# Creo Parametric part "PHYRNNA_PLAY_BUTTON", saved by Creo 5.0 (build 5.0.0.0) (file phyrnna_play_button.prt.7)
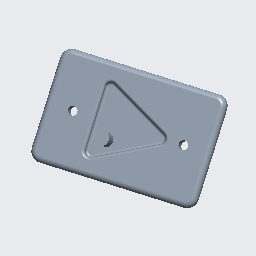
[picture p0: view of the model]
Units: Inch lbm Second (Pro/E Default); INCH, POUND, SECS

Created from: INLBS_PART_SOLID.PRT

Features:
  1. datum plane "RIGHT"
  2. datum plane "TOP"
  3. datum plane "FRONT"
  4. coordinate system
  5. sketch "Sketch 1"
  6. extrusion "Extrude 1"
  7. sketch "Sketch 2", "A_3"
  8. extruded cut "Extrude 2"
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
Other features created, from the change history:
  round "Round 1" (2 times)
  sketch "Sketch 3"
  extrusion "Extrude 3"
  round "Round 2"

Other named items: BASE_S, BASE_E, PLAY_S, PLAY_E, PLAY_R, PEG_S, PEG_E, BASE_R_1, BASE_R_2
